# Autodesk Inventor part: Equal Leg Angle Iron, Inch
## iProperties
Title: Equal Leg Angle Iron, Inch
Author: Tom Cross
Shininess: 64.0
Angle Display Precision: 2
Document Length Units: 11272
Document Angle Units: 11286
Document Time Units: 11279
Document Mass Units: 11290
Document Length Units Precision: 3
Document Angle Units Precision: 2
Compacted: True
PropertySet Name: _Private Model Information
Created: 2002-04
Part Number: EQUAL LEG STEEL ANGLES
Description: Equal Leg Angle Iron, Inch
Document SubType Name: Modeling
Designer: 09050137
Control State: 0
Master: False
Checked Out: False
PropertySet Name: Design Tracking Control
Density: 0.0
Volumn: 0.0
Area: 0.0
PropertySet Name: Model Information
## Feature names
1. Extrusion1
